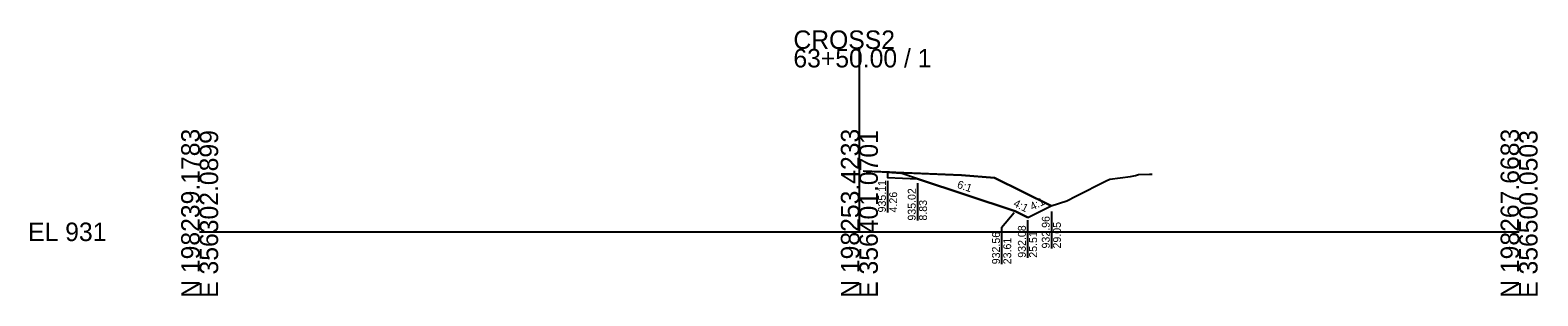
# Model space of a CAD drawing. Extents: x -26 to 203, y -10 to 14021.
# Drawn here: x -25.7 to 202.8, y 4490.3 to 4530.5 of the extents above; entities that cross this region are included whole.
import ezdxf

# ---------------------------------------------------------------- set-up
doc = ezdxf.new("R2010")
doc.units = 0
for name, color, linetype in [('Default', 7, 'Continuous'), ('P_E_XS_Ground', 7, 'Continuous'), ('P_XS', 7, 'Continuous'), ('P_XS_EAR_CommonGrnd', 7, 'Continuous'), ('P_XS_Lane', 7, 'Continuous'), ('P_XS_Rock', 7, 'Continuous')]:
    doc.layers.add(name, color=color, linetype=linetype)

msp = doc.modelspace()

# ---------------------------------------------------------------- linework, layer by layer
at = {"layer": 'Default'}
for p, q in [((100, 4500), (100, 4527.7)), ((0, 4500), (100, 4500)), ((100, 4500), (200, 4500))]:
    msp.add_line(p, q, dxfattribs=at)
at = {"layer": 'P_E_XS_Ground'}
for p, q in [((100.58, 4509.23), (101.05, 4509.18)), ((101.05, 4509.18), (115.5, 4508.6)), ((115.5, 4508.6), (120.5, 4508.2)), ((120.5, 4508.2), (129.05, 4503.93)), ((132.83, 4505.39), (137.43, 4507.73)), ((137.43, 4507.73), (137.97, 4507.97)), ((137.97, 4507.97), (141.08, 4508.39)), ((141.08, 4508.39), (141.87, 4508.55)), ((141.87, 4508.55), (142.32, 4508.66)), ((142.32, 4508.66), (143.99, 4508.71)), ((143.99, 4508.71), (144.38, 4508.72)), ((129.05, 4503.93), (131.46, 4504.68)), ((131.46, 4504.68), (132.83, 4505.39))]:
    msp.add_line(p, q, dxfattribs=at)
at = {"layer": 'P_XS'}
for p, q in [((100.58, 4509.23), (104.58, 4509.07)), ((104.26, 4509.05), (106.26, 4508.89)), ((108.83, 4508.04), (106.26, 4508.89))]:
    msp.add_line(p, q, dxfattribs=at)
at = {"layer": 'P_XS_EAR_CommonGrnd'}
msp.add_lwpolyline([(125.51, 4502.16), (129.05, 4503.93), (120.5, 4508.2), (115.5, 4508.6), (104.26, 4509.05), (104.26, 4508.22), (108.83, 4508.04), (123.61, 4503.11)], close=True, dxfattribs=at)
at = {"layer": 'P_XS_Lane'}
for p, q in [((104.26, 4509.05), (104.26, 4508.22)), ((104.26, 4508.22), (108.83, 4508.04)), ((123.61, 4503.11), (108.83, 4508.04)), ((125.51, 4502.16), (123.61, 4503.11)), ((125.51, 4502.16), (129.05, 4503.93))]:
    msp.add_line(p, q, dxfattribs=at)
at = {"layer": 'P_XS_Rock'}
for p, q in [((104.27, 4507.74), (104.27, 4502.94)), ((108.79, 4507.39), (108.79, 4501.7)), ((121.56, 4500.68), (123.47, 4502.95)), ((129.1, 4503.09), (129.1, 4497.48)), ((121.56, 4500.68), (121.56, 4495.08)), ((125.48, 4501.77), (125.48, 4496.08))]:
    msp.add_line(p, q, dxfattribs=at)

# ---------------------------------------------------------------- texts
at = {"layer": 'Default'}
for s, p in [('CROSS2', (90, 4527.7)), ('63+50.00 / 1', (90, 4524.9)), ('EL 931', (-26, 4498.6))]:
    msp.add_text(s, height=2.8, dxfattribs=at).set_placement(p)
for s, p in [('N 198239.1783', (0, 4490)), ('E 356302.0899', (2.8, 4490)), ('N 198253.4233', (100, 4490)), ('E 356401.0701', (102.8, 4490)), ('N 198267.6683', (200, 4490)), ('E 356500.0503', (202.8, 4490))]:
    msp.add_text(s, height=2.8, rotation=90, dxfattribs=at).set_placement(p)
at = {"layer": 'P_XS_Rock'}
for s, rotation, p in [('935.11', 90, (104.02, 4502.94)), ('6:1', 341.5651, (114.72, 4506.69)), ('4.26', 90, (105.72, 4502.94)), ('935.02', 90, (108.54, 4501.7)), ('8.83', 90, (110.24, 4501.7)), ('4:1', 333.4349, (123.23, 4503.93)), ('4:1', 26.5651, (126.23, 4503.21)), ('932.96', 90, (128.85, 4497.48)), ('932.56', 90, (121.31, 4495.09)), ('932.08', 90, (125.23, 4496.08)), ('25.51', 90, (126.93, 4496.08)), ('29.05', 90, (130.55, 4497.48)), ('23.61', 90, (123.01, 4495.09))]:
    msp.add_text(s, height=1.2, rotation=rotation, dxfattribs=at).set_placement(p)

doc.saveas('drawing.dxf')
